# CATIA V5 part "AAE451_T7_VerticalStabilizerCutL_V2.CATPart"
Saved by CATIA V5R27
Part number: VerticalStab
Bounding box of the stored display mesh (mm): x -0.013 to 222.987, y -11.19 to 10.719, z 0 to 225
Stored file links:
  W:\AAE 451\AAE451_T7_TailAssembly_V2\AAE451_T7_VerticalStabilizerCutL_V2.CATPart
  CATDrawing1.CATDrawing
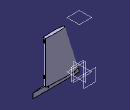
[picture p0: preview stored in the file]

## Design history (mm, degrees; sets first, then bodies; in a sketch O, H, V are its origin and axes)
Set1 "GeometryFromExcel"
  Point1: (1, 0.001, 0)
  Point2: (0.95, 0.0067, 0)
  Point3: (0.9, 0.0121, 0)
  Point4: (0.8, 0.0219, 0)
  Point5: (0.7, 0.0305, 0)
  Point6: (0.6, 0.038, 0)
  Point7: (0.5, 0.0441, 0)
  Point8: (0.4, 0.0484, 0)
  Point9: (0.3, 0.05, 0)
  Point10: (0.25, 0.0495, 0)
  Point11: (0.2, 0.0478, 0)
  Point12: (0.15, 0.0445, 0)
  Point13: (0.1, 0.039, 0)
  Point14: (0.075, 0.035, 0)
  Point15: (0.05, 0.0296, 0)
  Point16: (0.025, 0.0218, 0)
  Point17: (0.0125, 0.0158, 0)
  Point18: (0, 0, 0)
  Point19: (0.0125, -0.0158, 0)
  Point20: (0.025, -0.0218, 0)
  Point21: (0.05, -0.0296, 0)
  Point22: (0.075, -0.035, 0)
  Point23: (0.1, -0.039, 0)
  Point24: (0.15, -0.0445, 0)
  Point25: (0.2, -0.0478, 0)
  Point26: (0.25, -0.0495, 0)
  Point27: (0.3, -0.05, 0)
  Point28: (0.4, -0.0484, 0)
  Point29: (0.5, -0.0441, 0)
  Point30: (0.6, -0.038, 0)
  Point31: (0.7, -0.0305, 0)
  Point32: (0.8, -0.0219, 0)
  Point33: (0.9, -0.0121, 0)
  Point34: (0.95, -0.0067, 0)
  Point35: (1, -0.001, 0)
  Point36: (1, 0.001, 0)
  Point37: (0.95, 0.0067, 0)
  Point38: (0.9, 0.0121, 0)
  Point39: (0.8, 0.0219, 0)
  Point40: (0.7, 0.0305, 0)
  Point41: (0.6, 0.038, 0)
  Point42: (0.5, 0.0441, 0)
  Point43: (0.4, 0.0484, 0)
  Point44: (0.3, 0.05, 0)
  Point45: (0.25, 0.0495, 0)
  Point46: (0.2, 0.0478, 0)
  Point47: (0.15, 0.0445, 0)
  Point48: (0.1, 0.039, 0)
  Point49: (0.075, 0.035, 0)
  Point50: (0.05, 0.0296, 0)
  Point51: (0.025, 0.0218, 0)
  Point52: (0.0125, 0.0158, 0)
  Point53: (0, 0, 0)
  Point54: (0.0125, -0.0158, 0)
  Point55: (0.025, -0.0218, 0)
  Point56: (0.05, -0.0296, 0)
  Point57: (0.075, -0.035, 0)
  Point58: (0.1, -0.039, 0)
  Point59: (0.15, -0.0445, 0)
  Point60: (0.2, -0.0478, 0)
  Point61: (0.25, -0.0495, 0)
  Point62: (0.3, -0.05, 0)
  Point63: (0.4, -0.0484, 0)
  Point64: (0.5, -0.0441, 0)
  Point65: (0.6, -0.038, 0)
  Point66: (0.7, -0.0305, 0)
  Point67: (0.8, -0.0219, 0)
  Point68: (0.9, -0.0121, 0)
  Point69: (0.95, -0.0067, 0)
  Point70: (1, -0.001, 0)
  Curve1: Elements (Point36; Point37; Point38; Point39; Point40; Point41; Point42; Point43; Point44; Point45; Point46; Point47; Point48; Point49; Point50; Point51; Point52; Point53; Point54; Point55; Point56; Point57; Point58; Point59; Point60; Point61; Point62; Point63; Point64; Point65; Point66; Point67; Point68; Point69; Point70)
  Sketch1 on xy-plane, origin (0, 0, 0), H (1, 0, 0), V (0, 1, 0)
    projected curve E1 from edge of Curve1
    line L1 (1, 0.001) -> (1.0001, -0.001)
    point P3 (1, 0.001)
    point P4 (1.0001, -0.001)
    reference projected point E2 (1, 0.001) from Point1
    reference projected point E3 (1, -0.001) from Point35
    frozenspline C1
    line L2 (222.9868, -0.27) -> (222.9868, 0.1983)
    coincidence: P3 E2, P4 E3
    fix: C1
Body1 (main body)
  Plane1: type Offset, RefPlane xy-plane, Offset 225
  Sketch2 on xy-plane, origin (0, 0, 0), H (1, 0, 0), V (0, 1, 0)
    projected curve E1 from Sketch1.C1
    point P1 (222.9868, 0.1983)
    line L1 (222.9868, 0.1983) -> (222.9868, -0.27)
    point P3 (222.9868, 0.1983)
    coincidence: P3 P1
  Sketch3 on Plane1, origin (0, 0, 225), H (1, 0, 0), V (0, 1, 0)
    frozenspline C1
    line L1 (222.9868, 0.1983) -> (222.9868, -0.1225)
    fix: C1
  Loft1: solid, Sections (Sketch2; Sketch3)
  Plane2: type Offset, RefPlane zx-plane, Offset 50
  Sketch4 on Plane2, origin (0, 50, 0), H (0, 0, 1), V (1, 0, 0)
    line L1 (0, 227.8345) -> (23.3, 227.8345)
    line L2 (23.3, 227.8345) -> (23.3, -7.6138)
    line L3 (23.3, -7.6138) -> (0, -7.6138)
    line L4 (0, -7.6138) -> (0, 227.8345)
    reference projected line E1 (0, 222.9868) -> (0, -0.0132) from edge [face of Loft1 | face of Loft1]
    distance L4 L2 = 23.3
    distance L1 L3 = 235.4483
    vertical: L4 V, L2 V
    horizontal: L1 H, L3 H
    coincidence: L4 E1
  Pocket1: profile Sketch4, direction (0, -1, 0), up to zx-plane
  Sketch5 on zx-plane, origin (0, 0, 0), H (-1, 0, 0), V (0, 0, 1)
    line L1 (-222.9868, 225) -> (-167.2368, 225)
    line L2 (-167.2368, 225) -> (-167.2368, 23.3)
    line L3 (-167.2368, 23.3) -> (-222.9868, 23.3)
    line L4 (-222.9868, 23.3) -> (-222.9868, 225)
    reference projected line E1 (-7.2628, 23.3) -> (-222.9868, 23.3) from edge [face of Loft1 | face of Pocket1 from Sketch4.L2]
    reference projected line E2 (-222.9868, 23.3) -> (-222.9868, 225) from edge [face of Loft1 | face of Loft1]
    reference projected line E3 (-222.9868, 225) -> (-70.2471, 225) from edge [face of Loft1 | face of Loft1]
    distance L4 L2 = 55.75
    distance E3 L1 = 0
    horizontal: L1 H, L3 H
    vertical: L2 V, L4 V
    coincidence: L3 E1, L4 E2
  Pocket2: profile Sketch5, direction (0, -1, 0), through (limit type 3), opposite side through (limit type 3)
  Plane3: type Offset, RefPlane zx-plane, Offset 9, reversed
  Sketch6 on Plane3, origin (9.6807, -9, -4.8499), H (1, 0, 0), V (0, 0, -1)
    point P1 (13.3061, -16.4999)
    reference projected line E1 (213.3061, -4.8499) -> (-9.6939, -4.8499) from edge [face of Loft1 | face of Loft1]
    reference projected line E2 (157.5561, -28.1499) -> (213.3061, -28.1499) from edge [face of Loft1 | face of Pocket2 from Sketch5.L3]
    reference projected line E3 (213.3061, -4.8499) -> (213.3061, -28.1499) from edge [face of Loft1 | face of Loft1]
    distance P1 E3 = 200
    equidistance: E1 E2 P1
  Hole1: placed by Sketch6, at (22.9868, -9, 11.65) direction (0, 1, 0), diameter 5, through (limit type 6), counterbore diameter 15, counterbore depth 5
  RectPattern1: of Hole1, direction 1 instances 2, spacing 125, along xy-plane
  Sketch7 on face of Pocket2 from Sketch5.L2, origin (167.2368, 0, 0), H (0, 1, 0), V (0, 0, 1)
    construction line L1 (-5.5, 225) -> (5.5, 225)
    construction line L2 (5.5, 225) -> (5.5, 48.3)
    construction line L3 (5.5, 48.3) -> (-5.5, 48.3)
    construction line L4 (-5.5, 48.3) -> (-5.5, 225)
    reference intersected line E1 through (0, 225) direction (-1, 0) from Plane1
    line L5 (-0.5, 218) -> (0.5, 218)
    line L6 (0.5, 218) -> (0.5, 202)
    line L7 (0.5, 202) -> (-0.5, 202)
    line L8 (-0.5, 202) -> (-0.5, 218)
    line L9 (-0.5, 71.3) -> (0.5, 71.3)
    line L10 (0.5, 71.3) -> (0.5, 55.3)
    line L11 (0.5, 55.3) -> (-0.5, 55.3)
    line L12 (-0.5, 55.3) -> (-0.5, 71.3)
    point P11 (0.5, 55.3)
    distance L3 L1 = 176.7
    length L1 = 11
    length L11 = 1
    length L10 = 16
    distance L3 P11 = 7
    distance L5 L1 = 7
    length L6 = 16
    length L7 = 1
    horizontal: L1 H, L3 H, L5 H, L7 H, L9 H, L11 H
    vertical: L2 V, L4 V, L6 V, L8 V, L10 V, L12 V
    coincidence: L1 E1
    symmetry: L4 L2 V, L12 L10 V, L8 L6 V
  Pocket3: profile Sketch7, direction (-1, 0, 0), length 13.7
